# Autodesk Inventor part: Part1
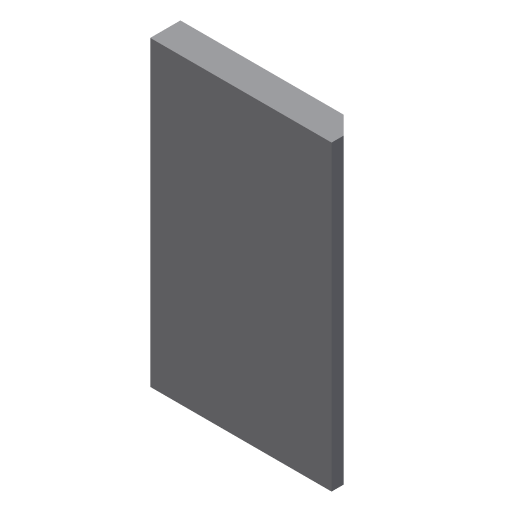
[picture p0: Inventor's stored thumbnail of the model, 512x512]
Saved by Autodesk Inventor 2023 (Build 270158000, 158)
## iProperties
Part Number: Part1
Document SubType Name: Modeling
Created: 2003-01
Designer: Owner
Density: 1 g/cm^3
Material: Generic
Appearance: Default
Control State: 0
Master: False
Checked Out: False
Shininess: 64.0
Length Units: 11269
Angle Units: 11279
Time Units: 11290
Mass Units: 11283
Length Display Precision: 3
Angle Display Precision: 2
Compacted: True
Density: 0.0
Volumn: 0.0
Area: 0.0
PropertySet Name: Model Information
Author: Owner
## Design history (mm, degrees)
sketch "Sketch1"
  geometry: L1 (-18.987, 24.241)-(11.013, 24.241); L2 (11.013, 24.241)-(11.013, -25.759); L3 (11.013, -25.759)-(-18.987, -25.759); L4 (-18.987, -25.759)-(-18.987, 24.241)
  constraints: 8 end point, 2 parallel, 1 horizontal, 1 perpendicular
  dimensions: "d0" = 30 distance of L1.start L1.end; "d1" = 50 distance of L3.end L1.start
extrude "Extrusion1" new body sketch "Sketch1" distance "d2" = 5; taper "d3" = 0 deg
chamfer "Chamfer1" distance "d4" = 3; stored, may be unused: second distance "d5" = 2, angle "d6" = 45 deg
body "Solid1"
